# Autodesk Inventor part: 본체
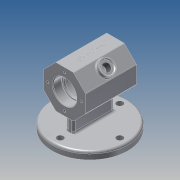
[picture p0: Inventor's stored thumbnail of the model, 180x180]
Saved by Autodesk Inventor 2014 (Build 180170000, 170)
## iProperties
Created: 2021-02
Part Number: 본체
Material: 알루미늄 6061
Document SubType Name: Modeling
Designer: kb542-23
Density: 2.71 g/cm^3
Appearance: 알루미늄 - 평지
Mass: 558.218 g
Surface Area: 510.265 cm^2
Volume: 205.984 cm^3
Author: kb542-23
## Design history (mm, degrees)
sketch "스케치1" dims "d0" = 58
  geometry: L1 (12.012, 29)-(29, 12.012); L2 (29, 12.012)-(29, -12.012); L3 (29, -12.012)-(12.012, -29); L4 (12.012, -29)-(-12.012, -29); L5 (-12.012, -29)-(-29, -12.012); L6 (-29, -12.012)-(-29, 12.012); L7 (-29, 12.012)-(-12.012, 29); L8 (-12.012, 29)-(12.012, 29); 4 further points
  constraints: 16 end point, 2 coincident, 2 vertical alignment, 1 midpoint, 19 other
extrude "돌출1" new body sketch "스케치1" stored distance "d2" = 70; taper "d3" = 0 deg
sketch "스케치2"
  geometry: L1 (-35, 12.012)-(-35, -12.012) reference; L2 (35, -12.012)-(35, 12.012) reference; L3 (-35, 0)-(35, 0); L4 (-23, 14)-(-20, 14); L5 (-20, 14)-(-20, 19); L6 (-17, 22)-(17, 22); L7 (20, 14)-(23, 14); L8 (23, 14)-(23, 15.7); L9 (23.3, 16)-(35, 16); L10 (-23.3, 16)-(-35, 16); L11 (-23, 14)-(-23, 15.7); L12 (20, 19)-(20, 14); L13 (-35, 16)-(-35, 0); L14 (35, 0)-(35, 16); A1 r 0.3 centre (-23.3, 15.7) between (-23, 15.7) and (-23.3, 16); A2 r 0.3 centre (23.3, 15.7) between (23.3, 16) and (23, 15.7); A3 r 3 centre (-17, 19) between (-17, 22) and (-20, 19); A4 r 3 centre (17, 19) between (20, 19) and (17, 22); 3 further points
  constraints: 24 end point, 8 point on circle, 8 tangent, 5 point on line, 4 centre point, 3 perpendicular, 2 collinear, 2 equal radius, 2 midpoint, 1 parallel, 1 vertical alignment
  dimensions: "d5" = 32 diameter of L10 L3; "d6" = 28 diameter of L4 L3; "d7" = 44 diameter of L6 L3; "d8" = 28 diameter of L7 L3; "d9" = 32 diameter of L9 L3; "d10" = 12 distance of point (-23, 16) L10.end; "d12" = 12 distance of point (23, 16) L9.end; "d13" = 3 distance of L4.start L4.end; "d14" = 3 distance of L7.start L7.end; "d15" = 0.3 radius of A1; "d16" = 40 distance between parallel lines of L12 L5; "d17" = 3 radius of A3
revolve "회전1" sketch "스케치2" stored, may be unused: angle "d18" = 90 deg
sketch "스케치3"
  geometry: A1 r 23 centre (0, 0) between (0, 23) and (-23, 0); 3 further points
  constraints: 4 point on circle, 1 centre point, 1 coincident
  dimensions: "d19" = 46 diameter of A1
hole "구멍1" sketch "스케치3" at (0, 23), (-23, 0), (0, -23), (23, 0) diameter "d20" = 3.242; stored, may be unused: countersink angle "d24" = 90 deg, drill point angle "d26" = 118 deg; dims "d21" = 8, "d22" = 4, "d23" = 2, "d25" = 10
node "작업 평면1"
sketch "스케치4"
  geometry: C1 r 52 at (0, 0); 1 further point
  constraints: 1 centre point, 1 coincident
  dimensions: "d28" = 104 diameter of C1
extrude "돌출2" join sketch "스케치4" distance "d29" = 10; taper "d30" = 0 deg
sketch "스케치5"
  geometry: A1 r 41 centre (0, 0) between (0, 41) and (-41, 0); 3 further points
  constraints: 4 point on circle, 1 centre point, 1 coincident
  dimensions: "d31" = 82 diameter of A1
hole "구멍2" sketch "스케치5" at (0, 41), (-41, 0), (0, -41), (41, 0) diameter "d32" = 9; stored, may be unused: countersink angle "d36" = 90 deg, drill point angle "d38" = 118 deg; dims "d33" = 9, "d34" = 4, "d35" = 2, "d37" = 10
sketch "스케치6"
  geometry: L1 (5, -28)-(-5, -28); L2 (-5, -28)-(-5, 28); L3 (-5, 28)-(5, 28); L4 (5, 28)-(5, -28); L5 (5, -28)-(-5, 28); L6 (-5, -28)-(5, 28); 1 further point
  constraints: 12 end point, 2 midpoint, 2 parallel, 1 horizontal, 1 perpendicular
  dimensions: "d40" = 10 distance of L2.end L3.end; "d41" = 56 distance of L3.end L1.start
extrude "돌출3" join sketch "스케치6" stored distance "d42" = 10; taper "d43" = 0 deg
node "작업 평면2"
sketch "스케치7"
  geometry: C1 r 10 at (-12.012, 35); 1 further point
  constraints: 1 centre point, 1 coincident
  dimensions: "d45" = 20 diameter of C1
extrude "돌출4" join sketch "스케치7" distance "d46" = 5; taper "d47" = 0 deg
sketch "스케치8"
  geometry: C1 r 10 at (0, 0) reference; C2 r 8 at (0, 0)
  constraints: 1 centre point, 1 coincident
  dimensions: "d48" = 16 diameter of C2
extrude "돌출5" cut sketch "스케치8" distance "d49" = 2; taper "d50" = 0 deg
sketch "스케치9"
  geometry: C1 r 8 at (0, 0) reference; 1 further point
  constraints: 1 coincident
hole "구멍3" sketch "스케치9" at (0, 0) diameter "d51" = 10.917; stored, may be unused: countersink angle "d55" = 90 deg, drill point angle "d57" = 118 deg; dims "d52" = 15, "d53" = 16, "d54" = 19.25, "d56" = 17.25
sketch "스케치10"
  geometry: L1 (-16.988, 0)-(-16.988, -70) reference; L2 (24.024, -70)-(0, -70) reference; 1 further point
  constraints: 1 other
  dimensions: "d58" = 29 distance from line of L1 point (12.012, -35); "d59" = 35 distance from line of point (12.012, -35) L2
feature "엠보싱1" sketch "스케치10" dims "d0" = 58, "d5" = 32, "d6" = 28, "d7" = 44, "d8" = 28, "d9" = 32, "d10" = 12, "d12" = 12, "d13" = 3, "d14" = 3, "d15" = 0.3, "d16" = 40, "d17" = 3, "d60" = 0.5, "d61" = 0
chamfer "모따기1" distance "d62" = 1; stored, may be unused: second distance "d63" = 2, angle "d64" = 45 deg
fillet "모깎기2" dims "d67" = 1, "d68" = 3
node "솔리드1"
mirror "대칭1"
other parameters: "d27" = -62, "d44" = 5
